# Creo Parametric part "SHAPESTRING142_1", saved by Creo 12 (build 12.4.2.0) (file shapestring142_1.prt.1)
Units: Custom; MM, KILOGRAM, SECS

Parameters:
  PTC_WM_ITERATION = "0"
  PTC_WM_VERSION = "-.0"
  PTC_WM_LIFECYCLE_STATE = "In Work"
  PTC_WM_LIFECYCLE = "MO_CADDocument"
  PTC_WM_CREATED_BY = "Maximilian Roepper (Z0017RMS: MO)"
  PTC_WM_CREATED_ON = "18-Sep-26 11:36:42 AM"
  PTC_WM_MODIFIED_BY = "Maximilian Roepper (Z0017RMS: MO)"
  PTC_WM_MODIFIED_ON = "18-Sep-26 11:36:46 AM"
  PDMLINKNUMBER = "PDM000071454832"
  PTC_WM_NAME = "shapestring142_1.prt"
  PTC_WM_NUMBER = "PDM000071454832"

Other parameters: WEIGHT, WEIGHT_FACTOR, WEIGHT_ADD, _MASS_TEMP, _DIFF_TEMP, MC_ERRORS, SUPPLIER

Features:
  1. coordinate system
  2. datum plane "PRT_YZ"
  3. datum plane "PRT_XY"
  4. datum plane "PRT_XZ"
  5. coordinate system
  6. datum axis
  7. datum axis
  8. datum axis
  9. coordinate system
  10. imported feature

Other named items: PRT, SIEMENS_MO, DRW_VIEW_ORG, PRT_X, PRT_Y, PRT_Z, CS0, ROUGH_GROB

Layers: 00_STD_CSYS-KSYS, 01_STD_PLANES-EBENEN, 02_STD_AXES-ACHSEN, 03_STD_CSYS-KSYS, 24_IMPORT_FEAT-IMPORT_KE, INTFCLR

Surfaces: 1 plane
